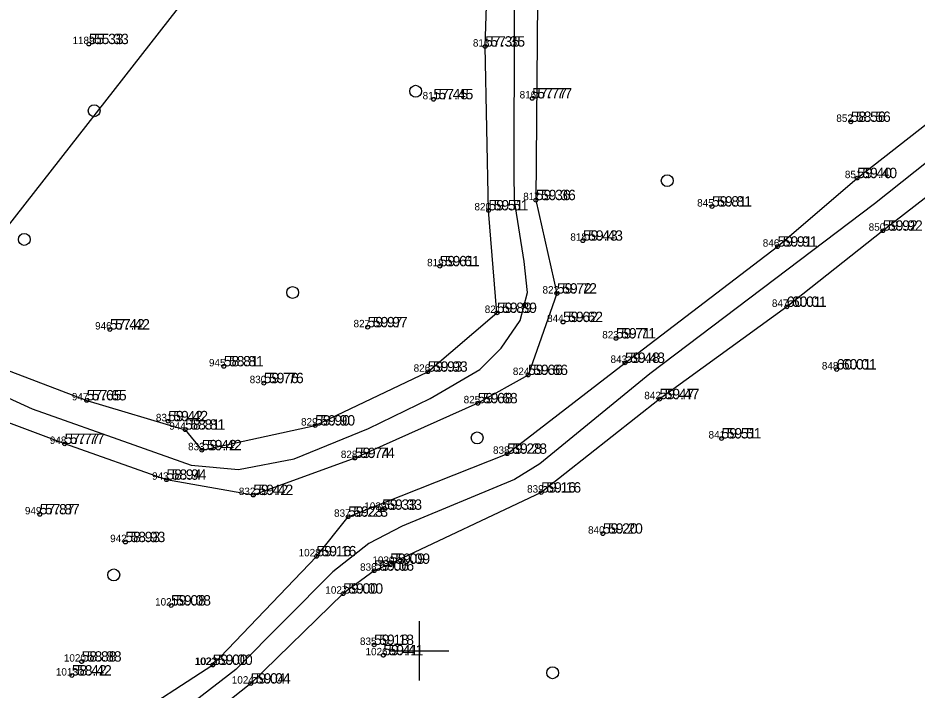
# Model space of a CAD drawing. Extents: x 554846 to 556995, y 6445875 to 6446723.
# Drawn here: x 555323 to 555383.6, y 6446097.4 to 6446142.7 of the extents above; entities that cross this region are included whole.
import ezdxf

# ---------------------------------------------------------------- set-up
doc = ezdxf.new("R2010")
doc.units = 0
for name, color, linetype in [('HALJASTUS', 7, 'Continuous'), ('KORGUS-EH2000', 7, 'Continuous'), ('MOOTKORG-EH2000', 7, 'Continuous'), ('MOOTMPUNKT', 7, 'Continuous'), ('MOOTNR', 7, 'Continuous'), ('SITRASS', 7, 'Continuous'), ('TEE', 7, 'Continuous'), ('VORK', 7, 'Continuous')]:
    doc.layers.add(name, color=color, linetype=linetype)

msp = doc.modelspace()

# ---------------------------------------------------------------- linework, layer by layer
at = {"layer": 'HALJASTUS'}
for centre in [(555349.766, 6446137.734), (555328.103, 6446136.415), (555366.719, 6446131.703), (555323.394, 6446127.745), (555341.477, 6446124.164), (555353.91, 6446114.363), (555329.422, 6446105.128), (555358.996, 6446098.531)]:
    msp.add_circle(centre, 0.4, dxfattribs=at)
at = {"layer": 'KORGUS-EH2000'}
for centre in [(555327.741, 6446140.909), (555354.451, 6446140.741), (555350.961, 6446137.187), (555357.623, 6446137.247), (555379.09, 6446135.665), (555379.516, 6446131.875), (555357.865, 6446130.39), (555354.678, 6446129.7), (555369.735, 6446129.958), (555381.245, 6446128.33), (555361.04, 6446127.658), (555374.157, 6446127.256), (555351.389, 6446125.933), (555359.29, 6446124.094), (555374.773, 6446123.196), (555355.246, 6446122.787), (555329.164, 6446121.669), (555346.531, 6446121.821), (555359.698, 6446122.174), (555363.266, 6446121.068), (555363.874, 6446119.42), (555336.839, 6446119.186), (555350.581, 6446118.824), (555357.341, 6446118.603), (555378.139, 6446118.975), (555339.532, 6446118.053), (555327.599, 6446116.893), (555366.199, 6446116.974), (555353.951, 6446116.697), (555333.086, 6446115.486), (555342.993, 6446115.198), (555334.239, 6446114.918), (555326.115, 6446113.958), (555370.38, 6446114.325), (555335.355, 6446113.531), (555355.929, 6446113.292), (555345.675, 6446113.007), (555332.979, 6446111.543), (555338.826, 6446110.512), (555358.225, 6446110.676), (555347.506, 6446109.517), (555324.436, 6446109.209), (555345.217, 6446109.048), (555362.383, 6446107.908), (555330.205, 6446107.337), (555343.079, 6446106.38), (555348.051, 6446105.874), (555346.97, 6446105.409), (555344.88, 6446103.864), (555333.283, 6446103.063), (555346.964, 6446100.407), (555327.259, 6446099.282), (555347.588, 6446099.709), (555336.092, 6446099.059), (555336.092, 6446099.058), (555326.596, 6446098.344), (555338.651, 6446097.801)]:
    msp.add_circle(centre, 0.125, dxfattribs=at)
at = {"layer": 'MOOTMPUNKT'}
for centre in [(555327.741, 6446140.909), (555354.451, 6446140.741), (555350.961, 6446137.187), (555357.623, 6446137.247), (555379.09, 6446135.665), (555379.516, 6446131.875), (555357.865, 6446130.39), (555354.678, 6446129.7), (555369.735, 6446129.958), (555381.245, 6446128.33), (555361.04, 6446127.658), (555374.157, 6446127.256), (555351.389, 6446125.933), (555359.29, 6446124.094), (555374.773, 6446123.196), (555355.246, 6446122.787), (555329.164, 6446121.669), (555346.531, 6446121.821), (555359.698, 6446122.174), (555363.266, 6446121.068), (555363.874, 6446119.42), (555336.839, 6446119.186), (555350.581, 6446118.824), (555357.341, 6446118.603), (555378.139, 6446118.975), (555339.532, 6446118.053), (555327.599, 6446116.893), (555366.199, 6446116.974), (555353.951, 6446116.697), (555333.086, 6446115.486), (555342.993, 6446115.198), (555334.239, 6446114.918), (555326.115, 6446113.958), (555370.38, 6446114.325), (555335.355, 6446113.531), (555355.929, 6446113.292), (555345.675, 6446113.007), (555332.979, 6446111.543), (555338.826, 6446110.512), (555358.225, 6446110.676), (555347.506, 6446109.517), (555324.436, 6446109.209), (555345.217, 6446109.048), (555362.383, 6446107.908), (555330.205, 6446107.337), (555343.079, 6446106.38), (555348.051, 6446105.874), (555346.97, 6446105.409), (555344.88, 6446103.864), (555333.283, 6446103.063), (555346.964, 6446100.407), (555327.259, 6446099.282), (555347.588, 6446099.709), (555336.092, 6446099.059), (555336.092, 6446099.058), (555326.596, 6446098.344), (555338.651, 6446097.801)]:
    msp.add_circle(centre, 0.125, dxfattribs=at)
at = {"layer": 'SITRASS'}
msp.add_lwpolyline([(555305.763, 6446088.513), (555311.729, 6446098.729), (555315.174, 6446103.591), (555318.557, 6446109.253), (555319.725, 6446114.115), (555320.34, 6446119.408), (555319.91, 6446123.531), (555321.017, 6446127.039), (555334.918, 6446144.825), (555339.434, 6446148.129), (555341.895, 6446149.324), (555360.137, 6446155.971), (555367.799, 6446158.187), (555388.114, 6446164.693), (555397.639, 6446165.994), (555410.433, 6446167.471), (555421.224, 6446169.405), (555430.679, 6446171.973), (555436.583, 6446173.098), (555447.304, 6446175.102), (555466.494, 6446179.217), (555474.824, 6446180.342)], dxfattribs=at)
at = {"layer": 'TEE'}
for points in [[(555319.047, 6446120.137), (555327.599, 6446116.893), (555334.239, 6446114.918), (555335.355, 6446113.531), (555342.993, 6446115.198), (555350.581, 6446118.824), (555355.246, 6446122.787), (555354.678, 6446129.7), (555354.451, 6446140.741), (555354.737, 6446149.692), (555354.606, 6446154.835), (555352.982, 6446170.446), (555353.572, 6446178.703), (555355.49, 6446184.295), (555358.278, 6446189.106), (555364.371, 6446194.497), (555368.709, 6446198.21), (555375.151, 6446199.451), (555387.148, 6446203.23)], [(555388.023, 6446199.971), (555376.051, 6446196.325), (555369.591, 6446194.402), (555365.972, 6446191.831), (555361.138, 6446187.251), (555359.011, 6446183.209), (555356.45, 6446170.618), (555358.144, 6446158.167), (555358.301, 6446151.752), (555357.987, 6446143.849), (555357.865, 6446130.39), (555359.29, 6446124.094), (555357.341, 6446118.603), (555353.951, 6446116.697), (555345.675, 6446113.007), (555338.826, 6446110.512), (555332.979, 6446111.543), (555326.115, 6446113.958), (555318.13, 6446116.963)], [(555316.356, 6446119.779), (555323.929, 6446116.329), (555330.766, 6446113.904), (555334.632, 6446112.533), (555337.821, 6446112.239), (555341.584, 6446112.963), (555346.599, 6446115), (555350.754, 6446117.027), (555354.083, 6446118.971), (555355.53, 6446120.419), (555356.812, 6446122.281), (555357.308, 6446124.163), (555357.071, 6446126.245), (555356.433, 6446130.358), (555356.398, 6446132.238), (555356.43, 6446142.409), (555356.459, 6446151.538)], [(555330.138, 6446095.193), (555336.092, 6446099.058), (555343.079, 6446106.38), (555345.217, 6446109.048), (555355.929, 6446113.292), (555363.874, 6446119.42), (555374.157, 6446127.256), (555379.516, 6446131.875), (555390.037, 6446140.091), (555397.814, 6446146.759), (555401.222, 6446148.095), (555412.213, 6446149.366), (555422.033, 6446151.944), (555425.956, 6446151.079), (555431.331, 6446146.995), (555436.284, 6446142.533), (555440.596, 6446133.14), (555440.927, 6446125.255), (555437.295, 6446117.463), (555428.215, 6446106.306), (555419.454, 6446099.97), (555414.313, 6446095.012)], [(555411.889, 6446096.584), (555419.563, 6446103.459), (555428.011, 6446111.351), (555434.853, 6446120.682), (555437.502, 6446124.533), (555436.993, 6446131.28), (555432.413, 6446140.005), (555428.739, 6446144.714), (555425.583, 6446147.254), (555422.273, 6446147.818), (555411.521, 6446145.9), (555402.569, 6446144.081), (555399.209, 6446142.919), (555390.695, 6446135.647), (555381.245, 6446128.33), (555374.773, 6446123.196), (555366.199, 6446116.974), (555358.225, 6446110.676), (555348.051, 6446105.874), (555346.97, 6446105.409), (555344.88, 6446103.864), (555338.651, 6446097.801), (555331.388, 6446092.027)], [(555390.782, 6446138.154), (555380.688, 6446130.154), (555365.551, 6446118.673), (555358.14, 6446112.612), (555356.424, 6446111.557), (555348.863, 6446108.416), (555346.609, 6446107.237), (555344.191, 6446105.334), (555337.65, 6446098.753), (555332.627, 6446094.864)]]:
    msp.add_lwpolyline(points, dxfattribs=at)
at = {"layer": 'VORK'}
for p, q in [((555350, 6446102), (555350, 6446098)), ((555348, 6446100), (555352, 6446100))]:
    msp.add_line(p, q, dxfattribs=at)

# ---------------------------------------------------------------- texts
at = {"layer": 'KORGUS-EH2000'}
for s, p in [('55.33', (555328.091, 6446140.909)), ('57.35', (555354.801, 6446140.741)), ('57.45', (555351.311, 6446137.187)), ('57.77', (555357.973, 6446137.247)), ('58.56', (555379.44, 6446135.665)), ('59.40', (555379.866, 6446131.875)), ('59.36', (555358.215, 6446130.39)), ('59.51', (555355.028, 6446129.7)), ('59.81', (555370.085, 6446129.958)), ('59.92', (555381.595, 6446128.33)), ('59.43', (555361.39, 6446127.658)), ('59.91', (555374.507, 6446127.256)), ('59.61', (555351.739, 6446125.933)), ('59.72', (555359.64, 6446124.094)), ('60.01', (555375.123, 6446123.196)), ('59.89', (555355.596, 6446122.787)), ('57.42', (555329.514, 6446121.669)), ('59.97', (555346.881, 6446121.821)), ('59.62', (555360.048, 6446122.174)), ('59.71', (555363.616, 6446121.068)), ('59.48', (555364.224, 6446119.42)), ('58.81', (555337.189, 6446119.186)), ('59.93', (555350.931, 6446118.824)), ('59.66', (555357.691, 6446118.603)), ('60.01', (555378.489, 6446118.975)), ('59.76', (555339.882, 6446118.053)), ('57.65', (555327.949, 6446116.893)), ('59.47', (555366.549, 6446116.974)), ('59.68', (555354.301, 6446116.697)), ('59.42', (555333.436, 6446115.486)), ('59.90', (555343.343, 6446115.198)), ('58.81', (555334.589, 6446114.918)), ('57.77', (555326.465, 6446113.958)), ('59.51', (555370.73, 6446114.325)), ('59.42', (555335.705, 6446113.531)), ('59.28', (555356.279, 6446113.292)), ('59.74', (555346.025, 6446113.007)), ('58.94', (555333.329, 6446111.543)), ('59.42', (555339.176, 6446110.512)), ('59.16', (555358.575, 6446110.676)), ('59.33', (555347.856, 6446109.517)), ('57.87', (555324.786, 6446109.209)), ('59.23', (555345.567, 6446109.048)), ('59.20', (555362.733, 6446107.908)), ('58.93', (555330.555, 6446107.337)), ('59.16', (555343.429, 6446106.38)), ('59.06', (555347.32, 6446105.409)), ('59.09', (555348.401, 6446105.874)), ('59.00', (555345.23, 6446103.864)), ('59.08', (555333.633, 6446103.063)), ('59.18', (555347.314, 6446100.407)), ('58.88', (555327.609, 6446099.282)), ('59.41', (555347.938, 6446099.709)), ('59.00', (555336.442, 6446099.059)), ('59.00', (555336.442, 6446099.058)), ('58.42', (555326.946, 6446098.344)), ('59.04', (555339.001, 6446097.801))]:
    msp.add_text(s, height=0.7, dxfattribs=at).set_placement(p)
at = {"layer": 'MOOTKORG-EH2000'}
for s, p in [('55.33', (555327.741, 6446140.909)), ('57.35', (555354.451, 6446140.741)), ('57.45', (555350.961, 6446137.187)), ('57.77', (555357.623, 6446137.247)), ('58.56', (555379.09, 6446135.665)), ('59.40', (555379.516, 6446131.875)), ('59.36', (555357.865, 6446130.39)), ('59.51', (555354.678, 6446129.7)), ('59.81', (555369.735, 6446129.958)), ('59.92', (555381.245, 6446128.33)), ('59.43', (555361.04, 6446127.658)), ('59.91', (555374.157, 6446127.256)), ('59.61', (555351.389, 6446125.933)), ('59.72', (555359.29, 6446124.094)), ('60.01', (555374.773, 6446123.196)), ('59.89', (555355.246, 6446122.787)), ('57.42', (555329.164, 6446121.669)), ('59.97', (555346.531, 6446121.821)), ('59.62', (555359.698, 6446122.174)), ('59.71', (555363.266, 6446121.068)), ('59.48', (555363.874, 6446119.42)), ('58.81', (555336.839, 6446119.186)), ('59.93', (555350.581, 6446118.824)), ('59.66', (555357.341, 6446118.603)), ('60.01', (555378.139, 6446118.975)), ('59.76', (555339.532, 6446118.053)), ('57.65', (555327.599, 6446116.893)), ('59.47', (555366.199, 6446116.974)), ('59.68', (555353.951, 6446116.697)), ('59.42', (555333.086, 6446115.486)), ('59.90', (555342.993, 6446115.198)), ('58.81', (555334.239, 6446114.918)), ('57.77', (555326.115, 6446113.958)), ('59.51', (555370.38, 6446114.325)), ('59.42', (555335.355, 6446113.531)), ('59.28', (555355.929, 6446113.292)), ('59.74', (555345.675, 6446113.007)), ('58.94', (555332.979, 6446111.543)), ('59.42', (555338.826, 6446110.512)), ('59.16', (555358.225, 6446110.676)), ('59.33', (555347.506, 6446109.517)), ('57.87', (555324.436, 6446109.209)), ('59.23', (555345.217, 6446109.048)), ('59.20', (555362.383, 6446107.908)), ('58.93', (555330.205, 6446107.337)), ('59.16', (555343.079, 6446106.38)), ('59.06', (555346.97, 6446105.409)), ('59.09', (555348.051, 6446105.874)), ('59.00', (555344.88, 6446103.864)), ('59.08', (555333.283, 6446103.063)), ('59.18', (555346.964, 6446100.407)), ('58.88', (555327.259, 6446099.282)), ('59.41', (555347.588, 6446099.709)), ('59.00', (555336.092, 6446099.059)), ('59.00', (555336.092, 6446099.058)), ('58.42', (555326.596, 6446098.344)), ('59.04', (555338.651, 6446097.801))]:
    msp.add_text(s, height=0.7, dxfattribs=at).set_placement(p)
at = {"layer": 'MOOTNR'}
for s, p in [('1189', (555326.641, 6446140.909)), ('813', (555353.626, 6446140.741)), ('811', (555350.236, 6446137.187)), ('816', (555356.773, 6446137.247)), ('852', (555378.115, 6446135.665)), ('851', (555378.691, 6446131.875)), ('817', (555357.015, 6446130.39)), ('845', (555368.735, 6446129.958)), ('820', (555353.728, 6446129.7)), ('850', (555380.295, 6446128.33)), ('818', (555360.19, 6446127.658)), ('846', (555373.157, 6446127.256)), ('819', (555350.539, 6446125.933)), ('822', (555358.315, 6446124.094)), ('847', (555373.773, 6446123.196)), ('821', (555354.421, 6446122.787)), ('844', (555358.623, 6446122.174)), ('946', (555328.164, 6446121.669)), ('827', (555345.581, 6446121.821)), ('823', (555362.341, 6446121.068)), ('843', (555362.899, 6446119.42)), ('945', (555335.839, 6446119.186)), ('826', (555349.631, 6446118.824)), ('848', (555377.139, 6446118.975)), ('824', (555356.316, 6446118.603)), ('830', (555338.582, 6446118.053)), ('947', (555326.599, 6446116.893)), ('825', (555353.001, 6446116.697)), ('842', (555365.174, 6446116.974)), ('831', (555332.261, 6446115.486)), ('829', (555342.043, 6446115.198)), ('944', (555333.164, 6446114.918)), ('841', (555369.505, 6446114.325)), ('948', (555325.115, 6446113.958)), ('833', (555334.43, 6446113.531)), ('828', (555344.725, 6446113.007)), ('838', (555354.979, 6446113.292)), ('943', (555332.004, 6446111.543)), ('832', (555337.851, 6446110.512)), ('839', (555357.275, 6446110.676)), ('949', (555323.436, 6446109.209)), ('1029', (555346.306, 6446109.517)), ('837', (555344.267, 6446109.048)), ('840', (555361.383, 6446107.908)), ('942', (555329.18, 6446107.337)), ('1028', (555341.879, 6446106.38)), ('1030', (555346.851, 6446105.874)), ('836', (555346.02, 6446105.409)), ('1027', (555343.68, 6446103.864)), ('1021', (555332.208, 6446103.063)), ('835', (555346.014, 6446100.407)), ('1026', (555346.388, 6446099.709)), ('1020', (555326.059, 6446099.282)), ('1022', (555334.867, 6446099.058)), ('1023', (555334.917, 6446099.059)), ('1013', (555325.521, 6446098.344)), ('1024', (555337.376, 6446097.801))]:
    msp.add_text(s, height=0.5, dxfattribs=at).set_placement(p)

doc.saveas('drawing.dxf')
